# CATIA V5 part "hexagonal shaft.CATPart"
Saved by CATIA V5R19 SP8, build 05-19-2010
Part number: hexagonal shaft
Bounding box of the stored display mesh (mm): x -23 to 146.206, y 126.6 to 133.6, z -18.721 to -10.639
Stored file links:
  G:\EU_thinkMotion\CFAO_2010\MMS_groupe1\MMS_groupe1\A reprendre\gduval\CFAO kinematic ok\hexagonal shaft.CATPart
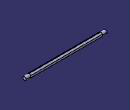
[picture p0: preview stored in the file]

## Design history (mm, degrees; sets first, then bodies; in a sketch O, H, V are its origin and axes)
Body1 (main body)
  Point1: stored without definition
  Point2: stored without definition
  Line1: type PtPt, FirstPoint Point1, SecondPoint Point2, Start 40, End 40
  Plane1: stored without definition
  Plane2: stored without definition
  Sketch1 on Plane1, origin (136.206, 0, 0), H (0, 1, 0), V (0, 0, 1)
    point P1 (130.1, -14.68)
    point P2 (133.6, -12.6593)
    point P3 (130.1, -10.6385)
    point P4 (126.6, -12.6593)
    point P5 (126.6, -16.7007)
    point P6 (130.1, -18.7215)
    point P7 (133.6, -16.7007)
    point P8 (131.85, -11.6489)
    line L1 (133.6, -12.6593) -> (130.1, -10.6385)
    line L2 (130.1, -10.6385) -> (126.6, -12.6593)
    line L3 (126.6, -12.6593) -> (126.6, -16.7007)
    line L4 (126.6, -16.7007) -> (130.1, -18.7215)
    line L5 (130.1, -18.7215) -> (133.6, -16.7007)
    line L6 (133.6, -16.7007) -> (133.6, -12.6593)
    construction line L7 (130.1, -14.68) -> (131.85, -11.6489)
    construction circle A1 centre (130.1, -14.68) radius 4.0415
    construction arc A2 centre (130.1, -18.7215) radius 4.0415 from (126.6, -16.7007) to (133.6, -16.7007) cw
    construction arc A3 centre (130.1, -10.6385) radius 4.0415 from (126.6, -12.6593) to (133.6, -12.6593) ccw
    reference projected point E1 (130.1, -14.68) from Line1
    axis line L8 (130.1, -10.6385) -> (130.1, -18.7215)
    distance L1 L4 = 7
    coincidence: A1 P2, A1 P3, A1 P4, A1 P5, A1 P6, A1 P7, A2 P1, A3 P1, P1 E1
    midpoint: P8 L1
    parallelism: L8 L3
    vertical: L8 V
  Pad1: profile Sketch1, direction (-1, 0, 0), up to Plane2, offset 1
  Sketch2 on end face of Pad1, origin (-13, 0, 0), H (0, -1, 0), V (0, 0, 1)
    circle A1 centre (-130.1, -14.68) radius 3.5
    point P1 (-130.1, -14.68)
    reference projected line E1 (-130.1, -10.6385) -> (-126.6, -12.6593) from edge [end face of Pad1 | face of Pad1 from Sketch1.L2]
    reference projected point E2 (-130.1, -14.68) from Line1
    tangency: E1 A1
    coincidence: P1 E2
  Pad2: profile Sketch2, direction (-1, 0, 0), length 10
  Sketch3 on start face of Pad1, origin (136.206, 0, 0), H (0, 1, 0), V (0, 0, 1)
    circle A1 centre (130.1, -14.68) radius 3.5
    point P1 (130.1, -14.68)
    reference projected line E1 (133.6, -12.6593) -> (130.1, -10.6385) from edge [face of Pad1 from Sketch1.L1 | start face of Pad1]
    reference projected point E2 (130.1, -14.68) from Line1
    tangency: A1 E1
    coincidence: E2 P1
  Pad3: profile Sketch3, direction (1, 0, 0), length 10
  Plane3: type OffsetPt, RefPlane xy-plane, RefPoint Point1
  Line2: type Normal, RefPoint Point1, RefSkin Plane3, Start -20, End 20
